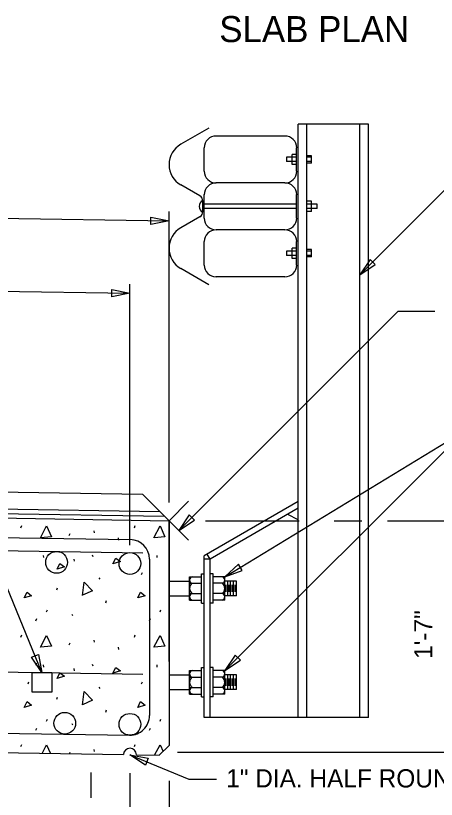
# Model space of a CAD drawing. Extents: x -2063 to 2068, y 79 to 1202.
# Drawn here: x -547 to -530.87, y 259.37 to 289.42 of the extents above; entities that cross this region are included whole.
import ezdxf

# ---------------------------------------------------------------- set-up
doc = ezdxf.new("R2010")
doc.units = 0
for name, color, linetype in [('BR_P_Drain_Object', 7, 'Continuous'), ('BR_P_Gen_Joint_Filler', 7, 'Continuous'), ('BR_P_Gen_Text', 7, 'Continuous'), ('BR_P_Gen_Utilities', 7, 'Continuous'), ('BR_P_Rail_Object', 7, 'Continuous'), ('BR_P_Slab_Object', 7, 'Continuous'), ('BR_P_Slab_Reinforcing', 7, 'Continuous'), ('BR_P_Sub_Reinforcing', 7, 'Continuous'), ('BR_X_Slab_Object', 7, 'Continuous'), ('BR_X_Slab_Reinforcing', 7, 'Continuous'), ('SH_Text', 7, 'Continuous')]:
    doc.layers.add(name, color=color, linetype=linetype)

msp = doc.modelspace()

# ---------------------------------------------------------------- linework, layer by layer
at = {"layer": 'BR_P_Drain_Object'}
for q in [(-540.369, 270.802), (-540.369, 269.302)]:
    msp.add_line((-541.119, 270.052), q, dxfattribs=at)
at = {"layer": 'BR_P_Gen_Joint_Filler'}
for p, q in [((-574.445, 270.935), (-541.474, 270.408)), ((-574.442, 270.76), (-541.296, 270.23))]:
    msp.add_line(p, q, dxfattribs=at)
at = {"layer": 'BR_P_Gen_Text'}
for p, q in [((-568.445, 281.991), (-541.119, 281.554)), ((-541.119, 270.752), (-541.119, 281.904)), ((-565.119, 279.137), (-542.619, 278.777)), ((-542.619, 269.109), (-542.619, 279.127)), ((-545.994, 264.225), (-549.51, 272.715)), ((-539.719, 270.052), (-536.126, 270.052)), ((-534.781, 270.052), (-533.728, 270.052)), ((-532.738, 270.052), (-527.168, 270.052)), ((-546.801, 269.784), (-546.765, 269.864)), ((-543.999, 269.664), (-543.99, 269.584)), ((-542.448, 269.784), (-542.413, 269.864)), ((-544.953, 269.48), (-544.917, 269.56)), ((-543.066, 269.39), (-543.057, 269.31)), ((-545.944, 268.715), (-545.935, 268.635)), ((-544.074, 268.738), (-544.039, 268.684)), ((-541.591, 268.715), (-541.582, 268.635)), ((-544.768, 268.574), (-544.759, 268.494)), ((-543.813, 267.858), (-543.777, 267.805)), ((-542.173, 267.99), (-542.138, 268.07)), ((-545.428, 267.402), (-545.393, 267.482)), ((-543.548, 266.907), (-543.513, 266.987)), ((-545.817, 266.552), (-545.782, 266.632)), ((-541.465, 266.552), (-541.429, 266.632)), ((-546.222, 266.216), (-546.186, 266.296)), ((-544.853, 266.469), (-544.817, 266.416)), ((-541.869, 266.216), (-541.833, 266.296)), ((-546.801, 265.589), (-546.765, 265.669)), ((-543.999, 265.469), (-543.99, 265.389)), ((-542.448, 265.589), (-542.413, 265.669)), ((-544.953, 265.285), (-544.917, 265.365)), ((-543.066, 265.195), (-543.057, 265.115)), ((-546.216, 264.587), (-546.225, 264.507)), ((-545.944, 264.52), (-545.935, 264.44)), ((-544.074, 264.543), (-544.039, 264.489)), ((-541.591, 264.52), (-541.582, 264.44)), ((-544.768, 264.379), (-544.759, 264.299)), ((-546.526, 263.795), (-546.491, 263.875)), ((-543.813, 263.663), (-543.777, 263.61)), ((-542.173, 263.795), (-542.138, 263.875)), ((-545.428, 263.207), (-545.393, 263.287)), ((-543.548, 262.712), (-543.513, 262.792)), ((-545.817, 262.357), (-545.782, 262.437)), ((-541.465, 262.357), (-541.429, 262.437)), ((-546.222, 262.021), (-546.186, 262.1)), ((-544.853, 262.274), (-544.817, 262.221)), ((-541.869, 262.021), (-541.833, 262.1)), ((-546.801, 261.394), (-546.765, 261.474)), ((-542.448, 261.394), (-542.413, 261.474)), ((-543.999, 261.274), (-543.99, 261.194)), ((-540.794, 261.176), (-530.318, 261.176)), ((-544.943, 261.112), (-544.917, 261.169)), ((-544.119, 260.399), (-544.119, 259.426)), ((-542.619, 260.375), (-542.619, 257.326)), ((-541.119, 260.075), (-541.119, 255.226))]:
    msp.add_line(p, q, dxfattribs=at)
for points in [[(-541.819, 281.694), (-541.119, 281.554), (-541.819, 281.414)], [(-543.319, 278.917), (-542.619, 278.777), (-543.319, 278.637)], [(-546.132, 264.926), (-545.994, 264.225), (-546.391, 264.819)]]:
    msp.add_lwpolyline(points, close=True, dxfattribs=at)
for points in [[(-546.055, 269.396), (-545.816, 269.849), (-545.629, 269.432), (-546.046, 269.396)], [(-541.702, 269.396), (-541.463, 269.849), (-541.276, 269.432), (-541.694, 269.396)], [(-545.413, 268.193), (-545.307, 268.415), (-545.129, 268.281), (-545.413, 268.193)], [(-543.269, 268.395), (-543.162, 268.617), (-542.985, 268.484), (-543.269, 268.395)], [(-544.442, 267.187), (-544.372, 267.694), (-544.054, 267.366), (-544.434, 267.19)], [(-546.674, 267.087), (-546.567, 267.309), (-546.389, 267.176), (-546.674, 267.087)], [(-542.321, 267.087), (-542.214, 267.309), (-542.037, 267.176), (-542.321, 267.087)], [(-546.055, 265.201), (-545.816, 265.654), (-545.629, 265.236), (-546.046, 265.201)], [(-541.702, 265.201), (-541.463, 265.654), (-541.276, 265.236), (-541.694, 265.201)], [(-545.413, 263.997), (-545.307, 264.219), (-545.129, 264.086), (-545.413, 263.997)], [(-543.269, 264.2), (-543.162, 264.422), (-542.985, 264.289), (-543.269, 264.2)], [(-544.442, 262.991), (-544.372, 263.499), (-544.054, 263.171), (-544.434, 262.994)], [(-546.674, 262.892), (-546.567, 263.114), (-546.389, 262.98), (-546.674, 262.892)], [(-542.321, 262.892), (-542.214, 263.114), (-542.037, 262.98), (-542.321, 262.892)], [(-545.99, 261.129), (-545.816, 261.459), (-545.666, 261.124)], [(-541.674, 261.06), (-541.463, 261.459), (-541.347, 261.201)]]:
    msp.add_lwpolyline(points, dxfattribs=at)
at = {"layer": 'BR_P_Gen_Utilities'}
msp.add_lwpolyline([(-546.368, 264.225), (-545.619, 264.225), (-545.619, 263.476), (-546.368, 263.476)], close=True, dxfattribs=at)
at = {"layer": 'BR_P_Rail_Object'}
for p, q in [((-540.331, 267.904), (-539.881, 267.904)), ((-540.331, 267.004), (-540.331, 267.904)), ((-539.881, 266.892), (-539.881, 268.017)), ((-539.881, 268.017), (-539.769, 268.017)), ((-539.432, 268.017), (-539.544, 268.017)), ((-539.432, 266.892), (-539.432, 268.017)), ((-538.981, 267.904), (-539.432, 267.904)), ((-538.981, 267.004), (-538.981, 267.904)), ((-541.119, 267.737), (-540.331, 267.737)), ((-540.331, 267.651), (-539.881, 267.651)), ((-538.981, 267.651), (-539.432, 267.651)), ((-538.533, 267.737), (-538.981, 267.737)), ((-538.926, 267.324), (-538.926, 267.596)), ((-538.869, 267.174), (-538.869, 267.737)), ((-538.814, 267.324), (-538.814, 267.596)), ((-538.757, 267.174), (-538.757, 267.737)), ((-538.701, 267.324), (-538.701, 267.596)), ((-538.645, 267.174), (-538.645, 267.737)), ((-538.589, 267.324), (-538.589, 267.596)), ((-538.533, 267.174), (-538.533, 267.737)), ((-540.331, 267.258), (-539.881, 267.258)), ((-538.981, 267.258), (-539.432, 267.258)), ((-541.119, 267.174), (-540.331, 267.174)), ((-540.331, 267.004), (-539.881, 267.004)), ((-538.981, 267.004), (-539.432, 267.004)), ((-538.533, 267.174), (-538.981, 267.174)), ((-540.331, 264.304), (-539.881, 264.304)), ((-540.331, 263.404), (-540.331, 264.304)), ((-539.881, 263.292), (-539.881, 264.416)), ((-539.881, 264.416), (-539.769, 264.416)), ((-539.432, 264.416), (-539.544, 264.416)), ((-539.432, 263.292), (-539.432, 264.416)), ((-538.981, 264.304), (-539.432, 264.304)), ((-538.981, 263.404), (-538.981, 264.304)), ((-541.119, 264.136), (-540.331, 264.136)), ((-540.331, 264.051), (-539.881, 264.051)), ((-538.981, 264.051), (-539.432, 264.051)), ((-538.533, 264.136), (-538.981, 264.136)), ((-538.926, 263.724), (-538.926, 263.996)), ((-538.869, 263.574), (-538.869, 264.136)), ((-538.814, 263.724), (-538.814, 263.996)), ((-538.757, 263.574), (-538.757, 264.136)), ((-538.701, 263.724), (-538.701, 263.996)), ((-538.645, 263.574), (-538.645, 264.136)), ((-538.589, 263.724), (-538.589, 263.996)), ((-538.533, 263.574), (-538.533, 264.136)), ((-540.331, 263.657), (-539.881, 263.657)), ((-538.981, 263.657), (-539.432, 263.657)), ((-541.119, 263.574), (-540.331, 263.574)), ((-540.331, 263.404), (-539.881, 263.404)), ((-539.881, 263.292), (-539.769, 263.292)), ((-539.432, 263.292), (-539.544, 263.292)), ((-538.981, 263.404), (-539.432, 263.404)), ((-538.533, 263.574), (-538.981, 263.574))]:
    msp.add_line(p, q, dxfattribs=at)
for centre, radius, start, end in [((-540.205, 267.775), 0.127, 94.208, 259.8734), ((-539.107, 267.775), 0.127, 280.1264, 85.7917), ((-540.097, 267.456), 0.234, 123.8536, 238.2461), ((-539.215, 267.456), 0.234, 301.7536, 56.1462), ((-540.203, 267.131), 0.128, 97.9594, 256.1115), ((-539.11, 267.131), 0.128, 283.8883, 82.0404), ((-540.205, 264.175), 0.127, 94.208, 259.8734), ((-539.107, 264.175), 0.127, 280.1264, 85.7917), ((-540.097, 263.856), 0.234, 123.8536, 238.2461), ((-539.215, 263.856), 0.234, 301.7536, 56.1462), ((-540.203, 263.53), 0.128, 97.9594, 256.1115), ((-539.11, 263.53), 0.128, 283.8883, 82.0404)]:
    msp.add_arc(centre, radius, start, end, dxfattribs=at)
at = {"layer": 'BR_P_Slab_Object'}
for p, q in [((-574.445, 271.586), (-542.135, 271.069)), ((-542.135, 271.069), (-541.119, 270.052)), ((-574.445, 270.585), (-541.119, 270.052)), ((-541.119, 270.052), (-541.119, 261.426)), ((-565.119, 261.435), (-542.869, 261.079)), ((-541.494, 261.057), (-541.119, 261.426)), ((-542.369, 261.071), (-541.494, 261.057))]:
    msp.add_line(p, q, dxfattribs=at)
msp.add_arc((-542.619, 261.075), 0.25, 359.0833, 179.0833, dxfattribs=at)
at = {"layer": 'BR_P_Slab_Reinforcing'}
for p, q in [((-549.369, 269.434), (-542.607, 269.326)), ((-541.869, 268.576), (-541.869, 262.575)), ((-565.131, 262.185), (-542.631, 261.825))]:
    msp.add_line(p, q, dxfattribs=at)
for centre, start, end in [((-542.619, 268.576), 0, 89.0833), ((-542.619, 262.575), 269.0833, 0)]:
    msp.add_arc(centre, 0.75, start, end, dxfattribs=at)
at = {"layer": 'BR_P_Sub_Reinforcing'}
for centre in [(-545.431, 268.454), (-542.619, 268.409), (-545.119, 262.282), (-542.619, 262.242)]:
    msp.add_circle(centre, 0.417, dxfattribs=at)
at = {"layer": 'BR_X_Slab_Object'}
for p, q in [((-536.168, 262.505), (-536.168, 285.255)), ((-533.468, 285.255), (-536.168, 285.255)), ((-535.831, 262.505), (-535.831, 285.255)), ((-533.806, 262.505), (-533.806, 285.255)), ((-533.468, 262.505), (-533.468, 285.255)), ((-539.588, 285.111), (-540.669, 284.487)), ((-536.675, 284.805), (-539.318, 284.805)), ((-539.769, 283.456), (-539.768, 284.355)), ((-536.225, 283.456), (-536.225, 284.355)), ((-536.225, 284.102), (-536.394, 284.102)), ((-536.393, 283.709), (-536.394, 284.102)), ((-535.662, 284.045), (-535.831, 284.045)), ((-535.662, 283.765), (-535.662, 284.045)), ((-536.225, 283.99), (-536.618, 283.99)), ((-536.618, 283.99), (-536.618, 283.822)), ((-536.225, 283.822), (-536.618, 283.822)), ((-535.662, 283.99), (-535.831, 283.99)), ((-535.662, 283.765), (-535.831, 283.765)), ((-535.662, 283.821), (-535.83, 283.821)), ((-536.224, 283.709), (-536.393, 283.709)), ((-539.937, 282.505), (-540.67, 282.928)), ((-536.675, 283.005), (-539.319, 283.006)), ((-539.769, 281.656), (-539.768, 282.556)), ((-536.225, 281.656), (-536.225, 282.556)), ((-539.824, 281.902), (-539.825, 282.311)), ((-535.662, 282.302), (-535.831, 282.302)), ((-535.662, 281.91), (-535.662, 282.302)), ((-536.225, 282.19), (-539.769, 282.19)), ((-536.224, 282.022), (-539.768, 282.022)), ((-535.437, 282.19), (-535.831, 282.19)), ((-535.437, 282.022), (-535.83, 282.022)), ((-535.437, 282.022), (-535.437, 282.19)), ((-539.937, 281.706), (-540.67, 281.284)), ((-535.662, 281.91), (-535.831, 281.91)), ((-536.675, 281.206), (-539.318, 281.207)), ((-539.769, 279.856), (-539.769, 280.756)), ((-536.225, 279.856), (-536.225, 280.756)), ((-536.225, 280.502), (-536.394, 280.502)), ((-536.393, 280.11), (-536.394, 280.502)), ((-535.662, 280.446), (-535.831, 280.446)), ((-535.662, 280.165), (-535.662, 280.446)), ((-536.225, 280.39), (-536.618, 280.39)), ((-536.618, 280.39), (-536.618, 280.223)), ((-536.225, 280.222), (-536.618, 280.223)), ((-536.225, 280.11), (-536.393, 280.11)), ((-535.662, 280.39), (-535.831, 280.39)), ((-535.662, 280.222), (-535.831, 280.222)), ((-535.662, 280.165), (-535.831, 280.165)), ((-539.588, 279.1), (-540.67, 279.724)), ((-536.675, 279.406), (-539.319, 279.406)), ((-541.119, 270.052), (-542.135, 271.069)), ((-536.168, 270.791), (-539.769, 268.709)), ((-536.173, 270.529), (-539.544, 268.58)), ((-536.173, 270.079), (-536.568, 270.288)), ((-541.119, 264.647), (-541.119, 270.052)), ((-539.769, 262.505), (-539.769, 268.709)), ((-539.544, 268.58), (-539.656, 268.774)), ((-539.544, 268.58), (-539.769, 268.58)), ((-539.544, 262.505), (-539.544, 268.58)), ((-539.881, 266.892), (-539.769, 266.892)), ((-539.432, 266.892), (-539.544, 266.892)), ((-533.468, 262.505), (-539.769, 262.505))]:
    msp.add_line(p, q, dxfattribs=at)
for centre, radius, start, end in [((-539.318, 284.355), 0.45, 89.997, 179.997), ((-536.674, 284.355), 0.45, 359.997, 89.997), ((-540.219, 283.707), 0.9, 119.9996, 239.9794), ((-539.318, 283.455), 0.45, 179.997, 269.997), ((-536.674, 283.455), 0.45, 269.997, 359.997), ((-539.318, 282.555), 0.45, 89.997, 179.997), ((-536.674, 282.555), 0.45, 359.997, 89.997), ((-539.715, 282.106), 0.249, 115.9139, 244.0801), ((-540.049, 282.31), 0.225, 359.997, 59.9856), ((-540.049, 281.901), 0.225, 300.0084, 359.997), ((-539.318, 281.656), 0.45, 179.997, 269.997), ((-536.674, 281.656), 0.45, 269.997, 359.997), ((-540.219, 280.504), 0.9, 120.0146, 239.9944), ((-539.318, 280.756), 0.45, 89.997, 179.997), ((-536.674, 280.756), 0.45, 359.997, 89.997), ((-539.318, 279.856), 0.45, 179.997, 269.997), ((-536.674, 279.856), 0.45, 269.997, 359.997)]:
    msp.add_arc(centre, radius, start, end, dxfattribs=at)
at = {"layer": 'BR_X_Slab_Reinforcing'}
for p, q in [((-578.445, 269.399), (-542.119, 268.818)), ((-578.445, 264.745), (-542.119, 264.163))]:
    msp.add_line(p, q, dxfattribs=at)
at = {"layer": 'SH_Text'}
for p, q in [((-533.806, 279.483), (-530.341, 282.947)), ((-540.744, 269.677), (-532.329, 278.092)), ((-532.329, 278.092), (-530.929, 278.092)), ((-538.981, 264.304), (-529.775, 273.51)), ((-538.981, 267.904), (-529.775, 273.51)), ((-542.619, 261.075), (-540.355, 260.137)), ((-540.355, 260.137), (-539.305, 260.137))]:
    msp.add_line(p, q, dxfattribs=at)
for points in [[(-533.407, 280.075), (-533.806, 279.483), (-533.21, 279.876)], [(-540.345, 270.27), (-540.744, 269.677), (-540.148, 270.071)], [(-538.454, 268.386), (-538.981, 267.904), (-538.309, 268.146)], [(-538.583, 264.896), (-538.981, 264.304), (-538.385, 264.697)], [(-542.024, 260.68), (-542.619, 261.075), (-541.918, 260.939)]]:
    msp.add_lwpolyline(points, close=True, dxfattribs=at)

# ---------------------------------------------------------------- texts
at = {"layer": 'BR_P_Gen_Text'}
for s, height, p in [('SLAB PLAN', 1, (-539.193, 288.405)), ('1" DIA. HALF ROUND', 0.70011, (-538.927, 259.82))]:
    msp.add_text(s, height=height, dxfattribs=at).set_placement(p)
msp.add_text('1\'-7"', height=0.7, rotation=90, dxfattribs=at).set_placement((-531.018, 264.753))

doc.saveas('drawing.dxf')
